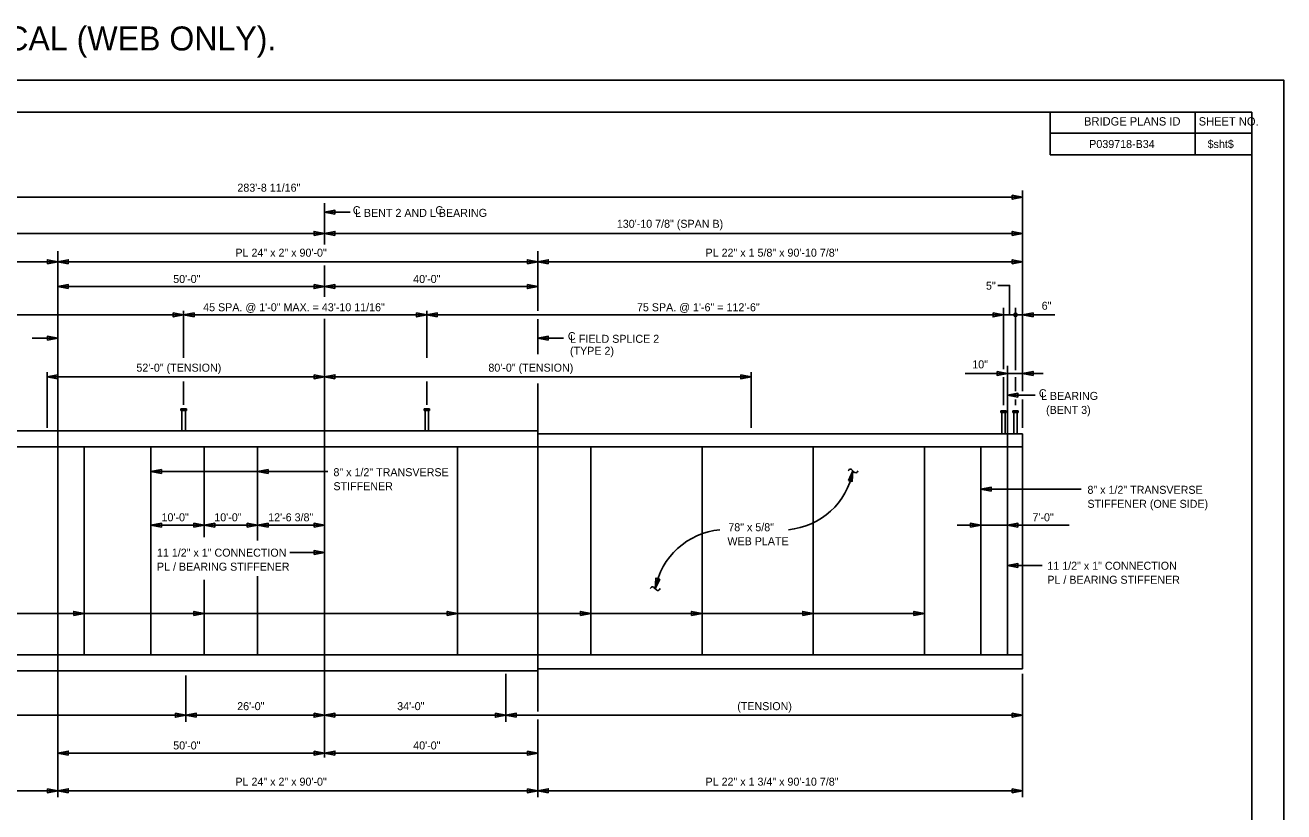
# Model space of a CAD drawing. Extents: x -383 to 14, y -392 to -94.
# Drawn here: x -239.8 to -161.2, y -145.2 to -96.1 of the extents above; entities that cross this region are included whole.
import ezdxf

# ---------------------------------------------------------------- set-up
doc = ezdxf.new("R2010")
doc.units = 0
for name, color, linetype in [('BR_AUTO DIMENSION', 7, 'Continuous'), ('BR_BORDER LINES', 7, 'Continuous'), ('BR_CENTER LINES', 7, 'Continuous'), ('BR_STRUCTURAL STEEL', 7, 'Continuous'), ('BR_TEXT', 7, 'Continuous'), ('Default', 7, 'Continuous'), ('Level 31', 7, 'Continuous')]:
    doc.layers.add(name, color=color, linetype=linetype)

msp = doc.modelspace()

# ---------------------------------------------------------------- linework, layer by layer
at = {"layer": 'BR_AUTO DIMENSION'}
for p, q in [((-272.075, -106.806), (-177.499, -106.806)), ((-177.499, -118.929), (-177.499, -106.393)), ((-221.135, -107.745), (-219.537, -107.745)), ((-272.075, -109.064), (-221.135, -109.064)), ((-221.135, -109.064), (-177.499, -109.064)), ((-257.802, -110.841), (-237.802, -110.841)), ((-237.802, -110.841), (-207.802, -110.841)), ((-207.802, -110.841), (-177.499, -110.841)), ((-221.135, -112.391), (-237.802, -112.391)), ((-207.802, -112.391), (-221.135, -112.391)), ((-229.936, -116.833), (-229.936, -113.909)), ((-214.733, -116.833), (-214.733, -113.909)), ((-178.694, -117.562), (-178.694, -113.71)), ((-177.944, -117.621), (-177.944, -113.71)), ((-267.936, -114.159), (-229.936, -114.159)), ((-229.936, -114.159), (-214.733, -114.159)), ((-214.733, -114.159), (-178.694, -114.159)), ((-175.491, -114.159), (-178.694, -114.159)), ((-237.802, -115.615), (-239.401, -115.615)), ((-207.802, -115.615), (-206.203, -115.615)), ((-238.469, -117.738), (-238.469, -121.213)), ((-194.469, -117.738), (-194.469, -121.213)), ((-181.098, -117.821), (-176.221, -117.821)), ((-238.469, -118.028), (-221.135, -118.028)), ((-229.936, -119.787), (-229.936, -118.317)), ((-194.469, -118.028), (-221.135, -118.028)), ((-214.733, -119.787), (-214.733, -118.317)), ((-178.694, -119.81), (-178.694, -118.048)), ((-177.944, -118.929), (-177.944, -118.048)), ((-178.444, -119.183), (-176.721, -119.183)), ((-177.944, -119.81), (-177.944, -119.447)), ((-177.499, -121.218), (-177.499, -119.447)), ((-231.98, -123.955), (-220.93, -123.955)), ((-180.11, -125.056), (-173.847, -125.056)), ((-174.586, -127.307), (-181.589, -127.307)), ((-221.135, -129.011), (-223.298, -129.011)), ((-178.444, -129.829), (-176.27, -129.829)), ((-183.642, -132.816), (-275.433, -132.816)), ((-229.802, -136.687), (-229.802, -139.586)), ((-209.802, -136.592), (-209.802, -139.586)), ((-177.499, -136.592), (-177.499, -144.298)), ((-229.802, -139.18), (-272.075, -139.18)), ((-221.135, -139.18), (-229.802, -139.18)), ((-209.802, -139.18), (-221.135, -139.18)), ((-177.499, -139.18), (-209.802, -139.18)), ((-221.135, -141.539), (-237.802, -141.539)), ((-207.802, -141.539), (-221.135, -141.539)), ((-257.802, -143.898), (-237.802, -143.898)), ((-237.802, -143.898), (-207.802, -143.898)), ((-207.802, -143.898), (-177.499, -143.898))]:
    msp.add_line(p, q, dxfattribs=at)
for points in [[(-178.149, -106.681), (-177.499, -106.806), (-178.149, -106.931)], [(-220.485, -107.87), (-221.135, -107.745), (-220.485, -107.62)], [(-221.785, -109.189), (-221.135, -109.064), (-221.785, -108.939)], [(-220.485, -109.189), (-221.135, -109.064), (-220.485, -108.939)], [(-178.149, -109.189), (-177.499, -109.064), (-178.149, -108.939)], [(-238.452, -110.966), (-237.802, -110.841), (-238.452, -110.716)], [(-237.152, -110.966), (-237.802, -110.841), (-237.152, -110.716)], [(-208.452, -110.966), (-207.802, -110.841), (-208.452, -110.716)], [(-207.152, -110.966), (-207.802, -110.841), (-207.152, -110.716)], [(-178.149, -110.966), (-177.499, -110.841), (-178.149, -110.716)], [(-237.152, -112.516), (-237.802, -112.391), (-237.152, -112.266)], [(-221.785, -112.266), (-221.135, -112.391), (-221.785, -112.516)], [(-220.485, -112.516), (-221.135, -112.391), (-220.485, -112.266)], [(-208.452, -112.266), (-207.802, -112.391), (-208.452, -112.516)], [(-230.586, -114.034), (-229.936, -114.159), (-230.586, -114.284)], [(-229.286, -114.284), (-229.936, -114.159), (-229.286, -114.034)], [(-215.383, -114.034), (-214.733, -114.159), (-215.383, -114.284)], [(-214.083, -114.284), (-214.733, -114.159), (-214.083, -114.034)], [(-179.344, -114.034), (-178.694, -114.159), (-179.344, -114.284)], [(-176.849, -114.284), (-177.499, -114.159), (-176.849, -114.034)], [(-238.452, -115.74), (-237.802, -115.615), (-238.452, -115.49)], [(-207.152, -115.74), (-207.802, -115.615), (-207.152, -115.49)], [(-237.819, -117.903), (-238.469, -118.028), (-237.819, -118.153)], [(-221.785, -117.903), (-221.135, -118.028), (-221.785, -118.153)], [(-220.485, -118.153), (-221.135, -118.028), (-220.485, -117.903)], [(-195.119, -117.903), (-194.469, -118.028), (-195.119, -118.153)], [(-179.094, -117.696), (-178.444, -117.821), (-179.094, -117.946)], [(-176.849, -117.946), (-177.499, -117.821), (-176.849, -117.696)], [(-177.794, -119.308), (-178.444, -119.183), (-177.794, -119.058)], [(-231.33, -124.08), (-231.98, -123.955), (-231.33, -123.83)], [(-224.663, -124.08), (-225.313, -123.955), (-224.663, -123.83)], [(-188.391, -124.504), (-188.108, -123.906), (-188.149, -124.566)], [(-179.46, -125.181), (-180.11, -125.056), (-179.46, -124.931)], [(-231.33, -127.432), (-231.98, -127.307), (-231.33, -127.182)], [(-229.297, -127.432), (-228.647, -127.307), (-229.297, -127.182)], [(-227.997, -127.432), (-228.647, -127.307), (-227.997, -127.182)], [(-225.963, -127.432), (-225.313, -127.307), (-225.963, -127.182)], [(-224.663, -127.432), (-225.313, -127.307), (-224.663, -127.182)], [(-221.785, -127.432), (-221.135, -127.307), (-221.785, -127.182)], [(-180.76, -127.432), (-180.11, -127.307), (-180.76, -127.182)], [(-177.794, -127.432), (-178.444, -127.307), (-177.794, -127.182)], [(-221.785, -129.136), (-221.135, -129.011), (-221.785, -128.886)], [(-177.794, -129.954), (-178.444, -129.829), (-177.794, -129.704)], [(-200.177, -130.673), (-200.459, -131.271), (-200.419, -130.611)], [(-236.808, -132.941), (-236.158, -132.816), (-236.808, -132.691)], [(-229.297, -132.941), (-228.647, -132.816), (-229.297, -132.691)], [(-213.461, -132.941), (-212.811, -132.816), (-213.461, -132.691)], [(-205.136, -132.941), (-204.486, -132.816), (-205.136, -132.691)], [(-198.188, -132.941), (-197.538, -132.816), (-198.188, -132.691)], [(-191.24, -132.941), (-190.59, -132.816), (-191.24, -132.691)], [(-184.292, -132.941), (-183.642, -132.816), (-184.292, -132.691)], [(-230.452, -139.055), (-229.802, -139.18), (-230.452, -139.305)], [(-229.152, -139.305), (-229.802, -139.18), (-229.152, -139.055)], [(-221.785, -139.055), (-221.135, -139.18), (-221.785, -139.305)], [(-220.485, -139.305), (-221.135, -139.18), (-220.485, -139.055)], [(-210.452, -139.055), (-209.802, -139.18), (-210.452, -139.305)], [(-209.152, -139.305), (-209.802, -139.18), (-209.152, -139.055)], [(-178.149, -139.055), (-177.499, -139.18), (-178.149, -139.305)], [(-237.152, -141.664), (-237.802, -141.539), (-237.152, -141.414)], [(-221.785, -141.414), (-221.135, -141.539), (-221.785, -141.664)], [(-220.485, -141.664), (-221.135, -141.539), (-220.485, -141.414)], [(-208.452, -141.414), (-207.802, -141.539), (-208.452, -141.664)], [(-238.452, -143.773), (-237.802, -143.898), (-238.452, -144.023)], [(-237.152, -144.023), (-237.802, -143.898), (-237.152, -143.773)], [(-208.452, -143.773), (-207.802, -143.898), (-208.452, -144.023)], [(-207.152, -144.023), (-207.802, -143.898), (-207.152, -143.773)], [(-178.149, -143.773), (-177.499, -143.898), (-178.149, -144.023)]]:
    msp.add_lwpolyline(points, close=True, dxfattribs=at)
msp.add_lwpolyline([(-178.319, -114.159), (-178.319, -112.317), (-179.059, -112.317)], dxfattribs=at)
msp.add_lwpolyline([(-178.319, -114.159), (-178.319, -112.317), (-179.059, -112.317)], dxfattribs=at)
msp.add_circle((-177.944, -114.159), 0.111, dxfattribs=at)
for centre, start, end in [((-192.533, -123.102), 274.96239, 349.7037), ((-196.035, -132.075), 94.96239, 169.7037)]:
    msp.add_arc(centre, 4.497, start, end, dxfattribs=at)
at = {"layer": 'BR_BORDER LINES'}
for p, q in [((-163.178, -101.489), (-297.843, -101.489)), ((-175.788, -104.156), (-175.788, -101.489)), ((-166.722, -104.156), (-166.722, -101.489)), ((-163.178, -185.489), (-163.178, -101.489)), ((-175.788, -102.808), (-163.178, -102.808)), ((-166.722, -102.808), (-163.178, -102.808)), ((-163.178, -104.156), (-175.788, -104.156))]:
    msp.add_line(p, q, dxfattribs=at)
at = {"layer": 'BR_CENTER LINES'}
for p, q in [((-221.135, -107.17), (-221.135, -109.769)), ((-237.802, -110.184), (-237.802, -144.298)), ((-207.802, -110.184), (-207.802, -113.912)), ((-221.135, -111.078), (-221.135, -113.027)), ((-221.135, -114.397), (-221.135, -122.412)), ((-207.802, -114.419), (-207.802, -116.617)), ((-178.444, -117.333), (-178.444, -122.412)), ((-207.802, -118.453), (-207.802, -138.953)), ((-221.135, -135.412), (-221.135, -141.826)), ((-207.802, -139.444), (-207.802, -144.298))]:
    msp.add_line(p, q, dxfattribs=at)
at = {"layer": 'BR_STRUCTURAL STEEL'}
for p, q in [((-257.802, -121.412), (-237.802, -121.412)), ((-237.802, -121.412), (-207.802, -121.412)), ((-237.802, -121.412), (-237.802, -122.412)), ((-207.802, -121.412), (-207.802, -122.412)), ((-207.802, -121.6), (-177.499, -121.6)), ((-177.499, -122.412), (-177.499, -121.6)), ((-272.075, -122.412), (-177.499, -122.412)), ((-236.158, -122.412), (-236.158, -135.412)), ((-231.98, -122.412), (-231.98, -135.412)), ((-228.647, -122.412), (-228.647, -128.041)), ((-225.313, -122.412), (-225.313, -128.26)), ((-221.135, -122.412), (-221.135, -135.412)), ((-212.811, -122.412), (-212.811, -135.412)), ((-204.486, -122.412), (-204.486, -135.412)), ((-197.538, -122.412), (-197.538, -135.412)), ((-190.59, -122.412), (-190.59, -135.412)), ((-183.642, -122.412), (-183.642, -135.412)), ((-180.11, -122.412), (-180.11, -135.412)), ((-178.444, -122.412), (-178.444, -135.412)), ((-177.499, -122.412), (-177.499, -135.412)), ((-231.98, -127.307), (-221.135, -127.307)), ((-225.313, -130.484), (-225.313, -135.412)), ((-228.647, -130.718), (-228.647, -135.412)), ((-272.075, -135.412), (-177.499, -135.412)), ((-237.802, -135.412), (-237.802, -136.412)), ((-207.802, -135.412), (-207.802, -136.412)), ((-177.499, -135.412), (-177.499, -136.287)), ((-257.802, -136.412), (-237.802, -136.412)), ((-237.802, -136.412), (-207.802, -136.412)), ((-207.802, -136.287), (-177.499, -136.287))]:
    msp.add_line(p, q, dxfattribs=at)
at = {"layer": 'BR_TEXT'}
for p, q in [((-188.368, -123.853), (-188.41, -123.914)), ((-188.027, -123.98), (-188.19, -123.831)), ((-187.793, -123.914), (-187.823, -123.96)), ((-200.774, -131.263), (-200.745, -131.217)), ((-200.541, -131.197), (-200.378, -131.346)), ((-200.199, -131.324), (-200.157, -131.263))]:
    msp.add_line(p, q, dxfattribs=at)
for centre, radius, start, end in [((-188.27, -123.906), 0.111, 43.45189, 151.73747), ((-187.933, -123.899), 0.125, 221.00704, 330.80591), ((-200.635, -131.278), 0.125, 41.00704, 150.80591), ((-200.297, -131.271), 0.111, 223.45189, 331.73747)]:
    msp.add_arc(centre, radius, start, end, dxfattribs=at)
at = {"layer": 'Default'}
for p, q in [((-230.108, -120.037), (-230.108, -120.131)), ((-230.108, -120.037), (-229.764, -120.037)), ((-230.108, -120.131), (-229.764, -120.131)), ((-230.045, -120.131), (-230.045, -121.412)), ((-229.827, -120.131), (-229.827, -121.412)), ((-229.764, -120.037), (-229.764, -120.131)), ((-214.905, -120.037), (-214.905, -120.131)), ((-214.905, -120.037), (-214.561, -120.037)), ((-214.905, -120.131), (-214.561, -120.131)), ((-214.843, -120.131), (-214.843, -121.412)), ((-214.624, -120.131), (-214.624, -121.412)), ((-214.561, -120.037), (-214.561, -120.131)), ((-178.866, -120.162), (-178.866, -120.256)), ((-178.866, -120.162), (-178.522, -120.162)), ((-178.866, -120.256), (-178.522, -120.256)), ((-178.803, -120.256), (-178.803, -121.537)), ((-178.584, -120.256), (-178.584, -121.537)), ((-178.522, -120.162), (-178.522, -120.256)), ((-178.116, -120.162), (-178.116, -120.256)), ((-178.116, -120.162), (-177.772, -120.162)), ((-178.116, -120.256), (-177.772, -120.256)), ((-178.053, -120.256), (-178.053, -121.537)), ((-177.834, -120.256), (-177.834, -121.537)), ((-177.772, -120.162), (-177.772, -120.256))]:
    msp.add_line(p, q, dxfattribs=at)
at = {"layer": 'Level 31'}
msp.add_lwpolyline([(-305.176, -187.489), (-161.176, -187.489), (-161.176, -99.489), (-305.176, -99.489)], close=True, dxfattribs=at)

# ---------------------------------------------------------------- texts
at = {"layer": 'BR_AUTO DIMENSION'}
for s, p in [('283\'-8 11/16"', (-226.577, -106.46)), ('130\'-10 7/8" (SPAN B)', (-202.863, -108.717)), ('PL 24" x 2" x 90\'-0"', (-226.701, -110.522)), ('PL 22" x 1 5/8" x 90\'-10 7/8"', (-197.319, -110.522)), ('50\'-0"', (-230.59, -112.166)), ('40\'-0"', (-215.59, -112.166)), ('5"', (-179.791, -112.585)), ('45 SPA. @ 1\'-0" MAX. = 43\'-10 11/16"', (-228.716, -113.933)), ('75 SPA. @ 1\'-6" = 112\'-6"', (-201.605, -113.933)), ('6"', (-176.309, -113.839)), (' 80\'-0" (TENSION)', (-211.076, -117.708)), ('10"', (-180.647, -117.502)), ('78" x 5/8" ', (-195.894, -127.678)), ('WEB PLATE', (-195.952, -128.553)), ('26\'-0"', (-226.59, -138.86)), ('(TENSION)', (-195.337, -138.86)), ('50\'-0"', (-230.59, -141.314)), ('40\'-0"', (-215.59, -141.314)), ('PL 24" x 2" x 90\'-0"', (-226.701, -143.579)), ('PL 22" x 1 3/4" x 90\'-10 7/8"', (-197.319, -143.579))]:
    msp.add_text(s, height=0.5, rotation=360, dxfattribs=at).set_placement(p)
for s, p in [(' 52\'-0" (TENSION)', (-233.076, -117.708)), ('10\'-0"', (-231.319, -127.057)), ('10\'-0"', (-228.02, -127.057)), ('12\'-6 3/8"', (-224.653, -127.057)), ('7\'-0"', (-176.888, -127.057)), ('34\'-0"', (-216.59, -138.86))]:
    msp.add_text(s, height=0.5, dxfattribs=at).set_placement(p)
at = {"layer": 'BR_TEXT'}
for s, height, p in [('EXAGGERATED BY 6 VERTICAL (FLANGES ONLY) AND BY 2 VERTICAL (WEB ONLY).', 1.5, (-305.065, -97.636)), ('BRIDGE PLANS ID', 0.52, (-173.663, -102.327)), ('SHEET NO.', 0.52, (-166.499, -102.327)), ('P039718-B34', 0.5, (-173.338, -103.732)), ('$sht$', 0.5, (-165.939, -103.732)), ('C', 0.5, (-176.485, -119.306)), ('L BEARING', 0.5, (-176.353, -119.473)), ('(BENT 3)', 0.5, (-176.035, -120.348)), ('11 1/2" x 1" CONNECTION ', 0.5, (-175.956, -130.086)), ('PL / BEARING STIFFENER', 0.5, (-175.956, -130.961))]:
    msp.add_text(s, height=height, dxfattribs=at).set_placement(p)
for s, p in [('C', (-219.363, -107.869)), ('L BENT 2 AND L BEARING', (-219.227, -108.035)), ('C', (-214.203, -107.869)), ('C', (-205.925, -115.739)), ('L FIELD SPLICE 2', (-205.79, -115.905)), ('(TYPE 2)', (-205.79, -116.655)), ('8" x 1/2" TRANSVERSE', (-220.574, -124.24)), ('STIFFENER', (-220.574, -125.115)), ('8" x 1/2" TRANSVERSE', (-173.449, -125.341)), ('STIFFENER (ONE SIDE)', (-173.449, -126.216)), ('11 1/2" x 1" CONNECTION ', (-231.605, -129.268)), ('PL / BEARING STIFFENER', (-231.605, -130.143))]:
    msp.add_text(s, height=0.5, rotation=360, dxfattribs=at).set_placement(p)

doc.saveas('drawing.dxf')
